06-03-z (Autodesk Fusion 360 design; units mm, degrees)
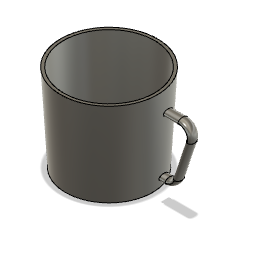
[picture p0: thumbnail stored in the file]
sketch "スケッチ1" plane through (0, 0, 0) normal (0, 0, 1) x axis (1, 0, 0)
  line L1 (0, 45) -> (0, 0)
  line L2 (-25, 45) -> (0, 45)
  line L3 (-22.5, 0) -> (-25, 45)
  line L4 (0, 0) -> (-22.5, 0)
  point P1 (0, 0)
  point P2 (0, 0)
  point P3 (0, 45)
  point P5 (-22.5, 0)
  coincident P1 P2
  vertical L1
  perpendicular L1 L2
  perpendicular L1 L4
  dimension "d1" = 50
  dimension "d2" distance P2 P3 = 45
  dimension "d3" distance L1 P5 = 45
revolve "回転" sketch "スケッチ1" AlongAngle 360
shell "シェル" innerThickness 1.5
offset_faces "面をオフセット" distance 1.5
sketch "スケッチ2" plane through (0, 0, 0) normal (0, 0, 1) x axis (1, 0, 0)
  line L1 (38.0629, 40) -> (24.7222, 40)
  line L2 (36.1396, 13.4189) -> (42.8063, 33.4189)
  line L3 (23.0556, 10) -> (31.3962, 10)
  line L4 (-22.5, 0) -> (-25, 45)
  line L5 (25, 45) -> (22.5, 0)
  line L6 (-22.5, 0) -> (22.5, 0)
  arc A1 centre (38.0629, 35) radius 5 clockwise from (38.0629, 40) to (42.8063, 33.4189)
  arc A2 centre (31.3962, 15) radius 5 clockwise from (36.1396, 13.4189) to (31.3962, 10)
  point P2 (24.7222, 40)
  point P5 (23.0556, 10)
  point P3 (45, 40)
  point P4 (35, 10)
  point P1 (0, 0)
  horizontal L1
  parallel L1 L3
  coincident P2 L5
  coincident P5 L5
  coincident P3 L1
  coincident P3 L2
  tangent L1 A1
  tangent L2 A1
  coincident P4 L2
  coincident P4 L3
  tangent L2 A2
  tangent L3 A2
  equal A1 A2
  dimension "d7" distance P1 P4 = 35
  dimension "d8" distance P1 P3 = 45
  dimension "d9" distance L3 L6 = 10
  dimension "d11" distance P3 P4 = 30
  dimension "d12" radius A1 = 5
work_plane "作業平面" PathDistance 0.1
sketch "スケッチ3" plane through (30.5693, 40, 0) normal (1, 0, 0) x axis (0, 1, 0)
  curve K1 (0, -2.5) -> (0, 2.5)
  curve K2 (1.5, 0) -> (-1.5, 0)
  closed curve K3 centre (0, 0)
  point P1 (0, 0)
  point P2 (0, 0)
  point P3 (0, 2.5)
  point P4 (0, -2.5)
  point P5 (-1.5, 0)
  point P6 (1.5, 0)
  coincident P1 P2
  vertical K1
  coincident K3 P3
  coincident K3 P4
  coincident K3 P5
  coincident K3 P6
  dimension "d14" = 3
  dimension "d15" distance K3 = 5
sweep "スイープ" sketch "スケッチ3" TwistAngle 0 TaperAngle 0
